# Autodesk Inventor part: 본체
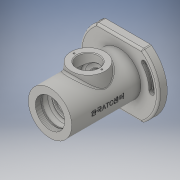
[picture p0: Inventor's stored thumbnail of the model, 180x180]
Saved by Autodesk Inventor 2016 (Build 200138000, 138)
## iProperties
Created: 2022-05
Part Number: 본체
Material: 일반
Document SubType Name: Modeling
Designer: PC-1-3
Density: 1 g/cm^3
Appearance: 기본값
Author: PC-1-3
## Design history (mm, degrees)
sketch "스케치2"
  geometry: L1 (0, 51)-(32, 51); L2 (32, 51)-(32, -51); L3 (32, -51)-(0, -51); L4 (0, -51)-(0, 51); L5 (0, -71.4)-(0, 71.4) reference; L6 (-6.4, 0)-(38.4, 0) reference; 1 further point
  constraints: 8 end point, 3 perpendicular, 1 horizontal, 1 point on line, 1 other
  dimensions: "d1" = 64 diameter of L2 L5; "d2" = 102 distance of L1.end L2.end
revolve "회전1" sketch "스케치2" stored, may be unused: angle "d3" = 90 deg
sketch "스케치3"
  geometry: L1 (33.985, -47)-(-33.985, -47); L2 (-33.985, -47)-(-33.985, 47); L3 (-33.985, 47)-(33.985, 47); L4 (33.985, 47)-(33.985, -47); L5 (33.985, -47)-(-33.985, 47); L6 (-33.985, -47)-(33.985, 47); A1 r 58 centre (0, 0) between (33.985, -47) and (33.985, 47); A2 r 58 centre (0, 0) between (-33.985, 47) and (-33.985, -47); 1 further point
  constraints: 12 end point, 4 point on circle, 3 midpoint, 2 centre point, 2 parallel, 1 horizontal, 1 perpendicular
  dimensions: "d6" = 94 distance of L1.end L2.end; "d7" = 58 radius of A2; "d8" = 58 radius of A1
extrude "돌출1" join sketch "스케치3" distance "d9" = 13; taper "d10" = 0 deg
sketch "스케치4"
  geometry: C1 r 36 at (0, 0); 1 further point
  constraints: 1 centre point, 1 coincident
  dimensions: "d11" = 72 diameter of C1
extrude "돌출2" join sketch "스케치4" distance "d12" = 3; taper "d13" = 0 deg
node "작업 평면1"
sketch "스케치5"
  geometry: L1 (-32, 51)-(32, 51) reference; C1 r 25 at (0, -5); 1 further point
  constraints: 1 centre point, 1 vertical alignment
  dimensions: "d15" = 50 diameter of C1; "d69" = 56 distance from line of L1 C1.centre
extrude "돌출3" join sketch "스케치5" stored distance "d16" = 3; taper "d17" = 0 deg
feature "면 기울기1" dims angle "d18" = 5 deg
sketch "스케치7"
  geometry: 2 further points
  constraints: 1 coincident
hole "구멍1" sketch "스케치7" at (0, 0) diameter "d19" = 43.376; stored, may be unused: countersink angle "d23" = 90 deg, drill point angle "d25" = 0 deg; dims "d20" = 8, "d21" = 4, "d22" = 2, "d24" = 8
sketch "스케치10"
  geometry: C1 r 24 at (0, 0); 1 further point
  constraints: 1 centre point, 1 coincident
  dimensions: "d26" = 48 diameter of C1
extrude "돌출4" cut sketch "스케치10" distance "d27" = 3; taper "d28" = 0 deg
sketch "스케치11"
  geometry: C1 r 22.5 at (0, 0); 1 further point
  constraints: 1 centre point, 1 coincident
  dimensions: "d29" = 45 diameter of C1
extrude "돌출5" cut sketch "스케치11" distance "d30" = 11; taper "d31" = 0 deg
sketch "스케치15"
  geometry: L1 (17.5, 29)-(17.5, 26.75); L2 (17.5, 26.75)-(18.5, 26.75); L3 (18.5, 26.75)-(18.5, 25); L4 (18.5, 25)-(17.5, 25); L5 (17.5, 25)-(17.5, 15); L6 (18.5, 14)-(24, 14); L7 (27, 11)-(27, -21); L8 (24, -24)-(18.5, -24); L9 (17.5, -25)-(17.5, -34.4); L10 (16.9, -35)-(15, -35); L11 (15, -35)-(15, -37); L12 (12, -40)-(11, -40); L13 (11, -40)-(11, -45.7); L14 (11, -45.7)-(14.5, -45.7); L15 (15, -46.2)-(15, -52.3); L16 (0, -86.2)-(0, 48.2) reference; L17 (-22.5, 29)-(22.5, 29) reference; L18 (15.404, -53)-(18.456, -53); L19 (20.897, -54.256)-(30, -67); L20 (-36, -67)-(36, -67) reference; L21 (18.5, -24)-(17.5, -25); L22 (15, -52.3)-(15.404, -53); L23 (18.5, 14)-(17.5, 15); L24 (17.5, 29)-(0, 29); L25 (0, 29)-(0, -67); L26 (0, -67)-(30, -67); A1 r 0.5 centre (14.5, -46.2) between (15, -46.2) and (14.5, -45.7); A2 r 3 centre (12, -37) between (12, -40) and (15, -37); A3 r 0.6 centre (16.9, -34.4) between (16.9, -35) and (17.5, -34.4); A4 r 3 centre (24, -21) between (24, -24) and (27, -21); A5 r 3 centre (18.456, -56) between (20.897, -54.256) and (18.456, -53); A6 r 3 centre (24, 11) between (27, 11) and (24, 14); 10 further points
  constraints: 46 end point, 22 point on line, 13 perpendicular, 12 point on circle, 12 tangent, 6 centre point, 2 equal radius, 2 midpoint, 2 vertical, 1 horizontal
  dimensions: "d38" = 35 diameter of L1 L16; "d39" = 37 diameter of L3 L16; "d40" = 1.75 distance of L2.end L3.end; "d41" = 4 vertical distance of L1.start L3.end; "d42" = 11 distance of L4.end point (17.5, 14); "d43" = 54 diameter of L7 L16; "d44" = 35 diameter of L9 L16; "d45" = 38 distance of point (27, 14) point (27, -24); "d46" = 11 distance of point (17.5, -24) point (17.5, -35); "d47" = 5 distance of L10.end point (15, -40); "d48" = 30 diameter of L11 L16; "d49" = 22 diameter of L13 L16; "d50" = 30 diameter of L15 L16; "d51" = 40 diameter of point (20, -53) L16; "d52" = 60 diameter of L19.end L16; "d53" = 7.3 distance of point (15, -45.7) point (15, -53); "d54" = 14 vertical distance of point (20, -53) L19.end; "d55" = 0.5 radius of A1; "d56" = 3 radius of A2; "d57" = 0.6 radius of A3; "d58" = 1 distance of L8.end point (17.5, -24); "d59" = 1 distance of L9.start point (17.5, -24) (= d58); "d60" = 0.7 distance of L15.end point (15, -53); "d61" = 30 deg angle of L15 L22; "d62" = 3 radius of A5; "d63" = 1 distance of L6.start point (17.5, 14); "d64" = 1 distance of L5.end point (17.5, 14) (= d63)
revolve "회전2" sketch "스케치15" stored, may be unused: angle "d65" = 90 deg
sketch "스케치19"
  geometry: C1 r 25 at (0, 0) reference; C2 r 16 at (0, 0); 1 further point
  constraints: 1 centre point, 1 coincident
  dimensions: "d70" = 32 diameter of C2
extrude "돌출8" cut sketch "스케치19" stored distance "d71" = 0; taper "d72" = 0 deg
sketch "스케치22" dims "d73" = 41
  geometry: C1 r 16 at (0, 0) reference; C2 r 25 at (0, 0) reference; 3 further points
  constraints: 1 coincident, 1 horizontal alignment, 2 other
hole "구멍2" sketch "스케치22" at (-20.5, 0) diameter "d74" = 2.459; stored, may be unused: countersink angle "d78" = 90 deg, drill point angle "d80" = 118 deg; dims "d75" = 6, "d76" = 4, "d77" = 2, "d79" = 8
sketch "스케치23" dims "d84" = 96
  geometry: L1 (0, 0)-(36.77, 30.854); L2 (0, 0)-(48, 0); A1 r 48 centre (0, 0) between (48, 0) and (36.77, 30.854); A2 r 52 centre (0, 0) between (52, 0) and (39.834, 33.425); A3 r 44 centre (0, 0) between (44, 0) and (33.706, 28.283); A4 r 4 centre (48, 0) between (44, 0) and (52, 0); A5 r 4 centre (36.77, 30.854) between (39.834, 33.425) and (33.706, 28.283); 3 further points
  constraints: 10 point on circle, 5 centre point, 4 end point, 4 tangent, 3 coincident, 2 horizontal alignment, 1 horizontal, 3 other
  dimensions: "d85" = 40 deg angle of L2 L1; "d86" = 4 radius of A5
extrude "돌출9" cut sketch "스케치23" distance "d87" = 4.4; taper "d88" = 0 deg
sketch "스케치25"
  geometry: A1 r 52 centre (0, 0) between (52, 0) and (39.834, 33.425) reference; A2 r 4 centre (36.77, 30.854) between (39.834, 33.425) and (33.706, 28.283) reference; A3 r 44 centre (0, 0) between (44, 0) and (33.706, 28.283) reference; A4 r 4 centre (48, 0) between (44, 0) and (52, 0) reference; A5 r 50.25 centre (0, 0) between (50.25, 0) and (38.494, 32.3); A6 r 2.25 centre (48, 0) between (45.75, 0) and (50.25, 0); A7 r 45.75 centre (0, 0) between (45.75, 0) and (35.047, 29.408); A8 r 2.25 centre (36.77, 30.854) between (38.494, 32.3) and (35.047, 29.408); 1 further point
  constraints: 8 point on circle, 4 centre point, 3 other
  dimensions: "d100" = 2.25 radius of A8
extrude "돌출10" cut sketch "스케치25" stored distance "d101" = 4.4; taper "d102" = 0 deg
hole "구멍3" diameter "d91" = 8; stored, may be unused: countersink angle "d95" = 90 deg, drill point angle "d97" = 118 deg; dims "d92" = 6, "d93" = 4, "d94" = 2, "d96" = 8, "d98" = 10, "d99" = 10
fillet "모깎기1" dims "d106" = 3
chamfer "모따기2" distance "d107" = 1; stored, may be unused: second distance "d108" = 2, angle "d109" = 45 deg
fillet "모깎기2" dims "d110" = 3
fillet "모깎기3" dims "d111" = 3
chamfer "모따기3" distance "d112" = 1; stored, may be unused: second distance "d113" = 2, angle "d114" = 45 deg
node "작업 평면2"
sketch "스케치28"
  geometry: L1 (5, 23)-(5, -27); L2 (5, -27)-(-5, -27); L3 (-5, -27)-(-5, 23); L4 (-5, 23)-(5, 23); L5 (0, 23)-(0, -27); L6 (5, -2)-(-5, -2); L7 (0, -81.4)-(0, 40.4) reference; L8 (-46.4, -64)-(46.4, -64) reference; 2 further points
  constraints: 5 midpoint, 4 end point, 1 point on line, 2 other
  dimensions: "d125" = 50 distance of L1.start L1.end; "d126" = 10 distance of L1.end L2.end; "d127" = 62 distance from line of L8 point (0, -2)
feature "엠보싱1" sketch "스케치28" dims "d1" = 64, "d2" = 102, "d128" = 0.5, "d129" = 0
chamfer "모따기7" distance "d130" = 1; stored, may be unused: second distance "d131" = 2, angle "d132" = 45 deg
node "솔리드1"
pattern_circular "원형 패턴1" dims angle "d82" = 360 deg
pattern_circular "원형 패턴2" dims "d104" = 360 deg
node "투영된 루프1"
node "투영된 루프2"
node "투영된 루프3"
other parameters: "d14" = 38, "d124" = 82.25
